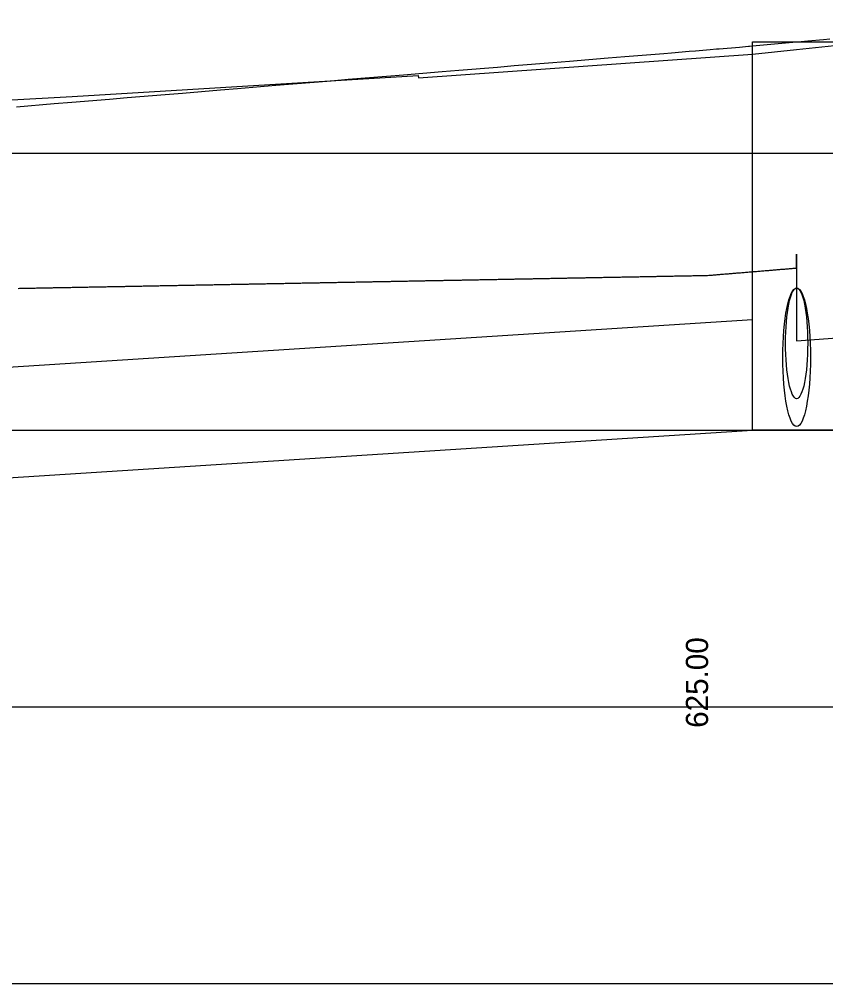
# Model space of a CAD drawing. Extents: x 2254979 to 2278074, y 13790855 to 13792793.
# Drawn here: x 2260664.4 to 2260737.2, y 13792141.4 to 13792228.5 of the extents above; entities that cross this region are included whole.
import ezdxf

# ---------------------------------------------------------------- set-up
doc = ezdxf.new("R2010")
doc.units = 0
for name, color, linetype in [('blank4', 7, 'Continuous'), ('D_DRN_PROF_HGL', 7, 'Continuous'), ('D_PROF_1', 7, 'Continuous'), ('D_PROF_NOTES_1', 7, 'Continuous'), ('Drain_PipeInside', 7, 'Continuous'), ('E_Terrain', 7, 'Continuous'), ('Inlet', 7, 'Continuous'), ('z - Construction', 7, 'Continuous')]:
    doc.layers.add(name, color=color, linetype=linetype)

msp = doc.modelspace()

# ---------------------------------------------------------------- linework, layer by layer
at = {"layer": 'blank4'}
msp.add_lwpolyline([(2259960.685, 13792141.443), (2259960.685, 13792316.443), (2261351.477, 13792316.443), (2261351.477, 13792141.443)], close=True, dxfattribs=at)
at = {"layer": 'D_DRN_PROF_HGL'}
msp.add_line((2260734.572, 13792207.324), (2260734.572, 13792199.492), dxfattribs=at)
for points in [[(2260664.271, 13792204.243), (2260664.382, 13792204.246), (2260664.493, 13792204.248), (2260664.603, 13792204.25), (2260664.714, 13792204.252), (2260664.824, 13792204.254), (2260664.935, 13792204.256), (2260665.045, 13792204.258), (2260665.156, 13792204.26), (2260665.267, 13792204.262), (2260665.377, 13792204.264), (2260665.488, 13792204.266), (2260665.598, 13792204.268), (2260665.709, 13792204.27), (2260665.819, 13792204.273), (2260665.93, 13792204.275), (2260666.041, 13792204.277), (2260666.151, 13792204.279), (2260666.262, 13792204.281), (2260666.372, 13792204.283), (2260666.483, 13792204.285), (2260666.593, 13792204.287), (2260666.704, 13792204.289), (2260666.815, 13792204.291), (2260666.925, 13792204.293), (2260667.036, 13792204.295), (2260667.146, 13792204.298), (2260667.257, 13792204.3), (2260667.367, 13792204.302), (2260667.478, 13792204.304), (2260667.589, 13792204.306), (2260667.699, 13792204.308), (2260667.81, 13792204.31), (2260667.92, 13792204.312), (2260668.031, 13792204.314), (2260668.141, 13792204.316), (2260668.252, 13792204.318), (2260668.363, 13792204.32), (2260668.473, 13792204.322), (2260668.584, 13792204.325), (2260668.694, 13792204.327), (2260668.805, 13792204.329), (2260668.916, 13792204.331), (2260669.026, 13792204.333), (2260669.137, 13792204.335), (2260669.247, 13792204.337), (2260669.358, 13792204.339), (2260669.468, 13792204.341), (2260669.579, 13792204.343), (2260669.69, 13792204.345), (2260669.8, 13792204.347), (2260669.911, 13792204.349), (2260670.021, 13792204.352), (2260670.132, 13792204.354), (2260670.242, 13792204.356), (2260670.353, 13792204.358), (2260670.464, 13792204.36), (2260670.574, 13792204.362), (2260670.685, 13792204.364), (2260670.795, 13792204.366), (2260670.906, 13792204.368), (2260671.016, 13792204.37), (2260671.127, 13792204.372), (2260671.238, 13792204.374), (2260671.348, 13792204.376), (2260671.459, 13792204.379), (2260671.569, 13792204.381), (2260671.68, 13792204.383), (2260671.79, 13792204.385), (2260671.901, 13792204.387), (2260672.012, 13792204.389), (2260672.122, 13792204.391), (2260672.233, 13792204.393), (2260672.343, 13792204.395), (2260672.454, 13792204.397), (2260672.564, 13792204.399), (2260672.675, 13792204.401), (2260672.786, 13792204.404), (2260672.896, 13792204.406), (2260673.007, 13792204.408), (2260673.117, 13792204.41), (2260673.228, 13792204.412), (2260673.338, 13792204.414), (2260673.449, 13792204.416), (2260673.56, 13792204.418), (2260673.67, 13792204.42), (2260673.781, 13792204.422), (2260673.891, 13792204.424), (2260674.002, 13792204.426), (2260674.113, 13792204.428), (2260674.223, 13792204.431), (2260674.334, 13792204.433), (2260674.444, 13792204.435), (2260674.555, 13792204.437), (2260674.665, 13792204.439), (2260674.776, 13792204.441), (2260674.887, 13792204.443), (2260674.997, 13792204.445), (2260675.108, 13792204.447), (2260675.218, 13792204.449), (2260675.329, 13792204.451), (2260675.439, 13792204.453), (2260675.55, 13792204.455), (2260675.661, 13792204.458), (2260675.771, 13792204.46), (2260675.882, 13792204.462), (2260675.992, 13792204.464), (2260676.103, 13792204.466), (2260676.213, 13792204.468), (2260676.324, 13792204.47), (2260676.435, 13792204.472), (2260676.545, 13792204.474), (2260676.656, 13792204.476), (2260676.766, 13792204.478), (2260676.877, 13792204.48), (2260676.987, 13792204.483), (2260677.098, 13792204.485), (2260677.209, 13792204.487), (2260677.319, 13792204.489), (2260677.43, 13792204.491), (2260677.54, 13792204.493), (2260677.651, 13792204.495), (2260677.761, 13792204.497), (2260677.872, 13792204.499), (2260677.983, 13792204.501), (2260678.093, 13792204.503), (2260678.204, 13792204.505), (2260678.314, 13792204.507), (2260678.425, 13792204.51), (2260678.535, 13792204.512), (2260678.646, 13792204.514), (2260678.757, 13792204.516), (2260678.867, 13792204.518), (2260678.978, 13792204.52), (2260679.088, 13792204.522), (2260679.199, 13792204.524), (2260679.31, 13792204.526), (2260679.42, 13792204.528), (2260679.531, 13792204.53), (2260679.641, 13792204.532), (2260679.752, 13792204.534), (2260679.862, 13792204.537), (2260679.973, 13792204.539), (2260680.084, 13792204.541), (2260680.194, 13792204.543), (2260680.305, 13792204.545), (2260680.415, 13792204.547), (2260680.526, 13792204.549), (2260680.636, 13792204.551), (2260680.747, 13792204.553), (2260680.858, 13792204.555), (2260680.968, 13792204.557), (2260681.079, 13792204.559), (2260681.189, 13792204.561), (2260681.3, 13792204.564), (2260681.41, 13792204.566), (2260681.521, 13792204.568), (2260681.632, 13792204.57), (2260681.742, 13792204.572), (2260681.853, 13792204.574), (2260681.963, 13792204.576), (2260682.074, 13792204.578), (2260682.184, 13792204.58), (2260682.295, 13792204.582), (2260682.406, 13792204.584), (2260682.516, 13792204.586), (2260682.627, 13792204.589), (2260682.737, 13792204.591), (2260682.848, 13792204.593), (2260682.958, 13792204.595), (2260683.069, 13792204.597), (2260683.18, 13792204.599), (2260683.29, 13792204.601), (2260683.401, 13792204.603), (2260683.511, 13792204.605), (2260683.622, 13792204.607), (2260683.732, 13792204.609), (2260683.843, 13792204.611), (2260683.954, 13792204.613), (2260684.064, 13792204.616), (2260684.175, 13792204.618), (2260684.285, 13792204.62), (2260684.396, 13792204.622), (2260684.507, 13792204.624), (2260684.617, 13792204.626), (2260684.728, 13792204.628), (2260684.838, 13792204.63), (2260684.949, 13792204.632), (2260685.059, 13792204.634), (2260685.17, 13792204.636), (2260685.281, 13792204.638), (2260685.391, 13792204.64), (2260685.502, 13792204.643), (2260685.612, 13792204.645), (2260685.723, 13792204.647), (2260685.833, 13792204.649), (2260685.944, 13792204.651), (2260686.055, 13792204.653), (2260686.165, 13792204.655), (2260686.276, 13792204.657), (2260686.386, 13792204.659), (2260686.497, 13792204.661), (2260686.607, 13792204.663), (2260686.718, 13792204.665), (2260686.829, 13792204.667), (2260686.939, 13792204.67), (2260687.05, 13792204.672), (2260687.16, 13792204.674), (2260687.271, 13792204.676), (2260687.381, 13792204.678), (2260687.492, 13792204.68), (2260687.603, 13792204.682), (2260687.713, 13792204.684), (2260687.824, 13792204.686), (2260687.934, 13792204.688), (2260688.045, 13792204.69), (2260688.155, 13792204.692), (2260688.266, 13792204.695), (2260688.377, 13792204.697), (2260688.487, 13792204.699), (2260688.598, 13792204.701), (2260688.708, 13792204.703), (2260688.819, 13792204.705), (2260688.929, 13792204.707), (2260689.04, 13792204.709), (2260689.151, 13792204.711), (2260689.261, 13792204.713), (2260689.372, 13792204.715), (2260689.482, 13792204.717), (2260689.593, 13792204.719), (2260689.704, 13792204.722), (2260689.814, 13792204.724), (2260689.925, 13792204.726), (2260690.035, 13792204.728), (2260690.146, 13792204.73), (2260690.256, 13792204.732), (2260690.367, 13792204.734), (2260690.478, 13792204.736), (2260690.588, 13792204.738), (2260690.699, 13792204.74), (2260690.809, 13792204.742), (2260690.92, 13792204.744), (2260691.03, 13792204.746), (2260691.141, 13792204.749), (2260691.252, 13792204.751), (2260691.362, 13792204.753), (2260691.473, 13792204.755), (2260691.583, 13792204.757), (2260691.694, 13792204.759), (2260691.804, 13792204.761), (2260691.915, 13792204.763), (2260692.026, 13792204.765), (2260692.136, 13792204.767), (2260692.247, 13792204.769), (2260692.357, 13792204.771), (2260692.468, 13792204.774), (2260692.578, 13792204.776), (2260692.689, 13792204.778), (2260692.8, 13792204.78), (2260692.91, 13792204.782), (2260693.021, 13792204.784), (2260693.131, 13792204.786), (2260693.242, 13792204.788), (2260693.352, 13792204.79), (2260693.463, 13792204.792), (2260693.574, 13792204.794), (2260693.684, 13792204.796), (2260693.795, 13792204.798), (2260693.905, 13792204.801), (2260694.016, 13792204.803), (2260694.126, 13792204.805), (2260694.237, 13792204.807), (2260694.348, 13792204.809), (2260694.458, 13792204.811), (2260694.569, 13792204.813), (2260694.679, 13792204.815), (2260694.79, 13792204.817), (2260694.901, 13792204.819), (2260695.011, 13792204.821), (2260695.122, 13792204.823), (2260695.232, 13792204.825), (2260695.343, 13792204.828), (2260695.453, 13792204.83), (2260695.564, 13792204.832), (2260695.675, 13792204.834), (2260695.785, 13792204.836), (2260695.896, 13792204.838), (2260696.006, 13792204.84), (2260696.117, 13792204.842), (2260696.227, 13792204.844), (2260696.338, 13792204.846), (2260696.449, 13792204.848), (2260696.559, 13792204.85), (2260696.67, 13792204.852), (2260696.78, 13792204.855), (2260696.891, 13792204.857), (2260697.001, 13792204.859), (2260697.112, 13792204.861), (2260697.223, 13792204.863), (2260697.333, 13792204.865), (2260697.444, 13792204.867), (2260697.554, 13792204.869), (2260697.665, 13792204.871), (2260697.775, 13792204.873), (2260697.886, 13792204.875), (2260697.997, 13792204.877), (2260698.107, 13792204.88), (2260698.218, 13792204.882), (2260698.328, 13792204.884), (2260698.439, 13792204.886), (2260698.549, 13792204.888), (2260698.66, 13792204.89), (2260698.771, 13792204.892), (2260698.881, 13792204.894), (2260698.992, 13792204.896), (2260699.102, 13792204.898), (2260699.213, 13792204.9), (2260699.323, 13792204.902), (2260699.434, 13792204.904), (2260699.545, 13792204.907), (2260699.655, 13792204.909), (2260699.766, 13792204.911), (2260699.876, 13792204.913), (2260699.987, 13792204.915), (2260700.098, 13792204.917), (2260700.208, 13792204.919), (2260700.319, 13792204.921), (2260700.429, 13792204.923), (2260700.54, 13792204.925), (2260700.65, 13792204.927), (2260700.761, 13792204.929), (2260700.872, 13792204.931), (2260700.982, 13792204.934), (2260701.093, 13792204.936), (2260701.203, 13792204.938), (2260701.314, 13792204.94), (2260701.424, 13792204.942), (2260701.535, 13792204.944), (2260701.646, 13792204.946), (2260701.756, 13792204.948), (2260701.867, 13792204.95), (2260701.977, 13792204.952), (2260702.088, 13792204.954), (2260702.198, 13792204.956), (2260702.309, 13792204.959), (2260702.42, 13792204.961), (2260702.53, 13792204.963), (2260702.641, 13792204.965), (2260702.751, 13792204.967), (2260702.862, 13792204.969), (2260702.972, 13792204.971), (2260703.083, 13792204.973), (2260703.194, 13792204.975), (2260703.304, 13792204.977), (2260703.415, 13792204.979), (2260703.525, 13792204.981), (2260703.636, 13792204.983), (2260703.746, 13792204.986), (2260703.857, 13792204.988), (2260703.968, 13792204.99), (2260704.078, 13792204.992), (2260704.189, 13792204.994), (2260704.299, 13792204.996), (2260704.41, 13792204.998), (2260704.52, 13792205), (2260704.631, 13792205.002), (2260704.742, 13792205.004), (2260704.852, 13792205.006), (2260704.963, 13792205.008), (2260705.073, 13792205.01), (2260705.184, 13792205.013), (2260705.294, 13792205.015), (2260705.405, 13792205.017), (2260705.516, 13792205.019), (2260705.626, 13792205.021), (2260705.737, 13792205.023), (2260705.847, 13792205.025), (2260705.958, 13792205.027), (2260706.069, 13792205.029), (2260706.179, 13792205.031), (2260706.29, 13792205.033), (2260706.4, 13792205.035), (2260706.511, 13792205.037), (2260706.621, 13792205.04), (2260706.732, 13792205.042), (2260706.843, 13792205.044), (2260706.953, 13792205.046), (2260707.064, 13792205.048), (2260707.174, 13792205.05), (2260707.285, 13792205.052), (2260707.395, 13792205.054), (2260707.506, 13792205.056), (2260707.617, 13792205.058), (2260707.727, 13792205.06), (2260707.838, 13792205.062), (2260707.948, 13792205.065), (2260708.059, 13792205.067), (2260708.169, 13792205.069), (2260708.28, 13792205.071), (2260708.391, 13792205.073), (2260708.501, 13792205.075), (2260708.612, 13792205.077), (2260708.722, 13792205.079), (2260708.833, 13792205.081), (2260708.943, 13792205.083), (2260709.054, 13792205.085), (2260709.165, 13792205.087), (2260709.275, 13792205.089), (2260709.386, 13792205.092), (2260709.496, 13792205.094), (2260709.607, 13792205.096), (2260709.717, 13792205.098), (2260709.828, 13792205.1), (2260709.939, 13792205.102), (2260710.049, 13792205.104), (2260710.16, 13792205.106), (2260710.27, 13792205.108), (2260710.381, 13792205.11), (2260710.491, 13792205.112), (2260710.602, 13792205.114), (2260710.713, 13792205.116), (2260710.823, 13792205.119), (2260710.934, 13792205.121), (2260711.044, 13792205.123), (2260711.155, 13792205.125), (2260711.266, 13792205.127), (2260711.376, 13792205.129), (2260711.487, 13792205.131), (2260711.597, 13792205.133), (2260711.708, 13792205.135), (2260711.818, 13792205.137), (2260711.929, 13792205.139), (2260712.04, 13792205.141), (2260712.15, 13792205.144), (2260712.261, 13792205.146), (2260712.371, 13792205.148), (2260712.482, 13792205.15), (2260712.592, 13792205.152), (2260712.703, 13792205.154), (2260712.814, 13792205.156), (2260712.924, 13792205.158), (2260713.035, 13792205.16), (2260713.145, 13792205.162), (2260713.256, 13792205.164), (2260713.366, 13792205.166), (2260713.477, 13792205.168), (2260713.588, 13792205.171), (2260713.698, 13792205.173), (2260713.809, 13792205.175), (2260713.919, 13792205.177), (2260714.03, 13792205.179), (2260714.14, 13792205.181), (2260714.251, 13792205.183), (2260714.362, 13792205.185), (2260714.472, 13792205.187), (2260714.583, 13792205.189), (2260714.693, 13792205.191), (2260714.804, 13792205.193), (2260714.914, 13792205.195), (2260715.025, 13792205.198), (2260715.136, 13792205.2), (2260715.246, 13792205.202), (2260715.357, 13792205.204), (2260715.467, 13792205.206), (2260715.578, 13792205.208), (2260715.688, 13792205.21), (2260715.799, 13792205.212), (2260715.91, 13792205.214), (2260716.02, 13792205.216), (2260716.131, 13792205.218), (2260716.241, 13792205.22), (2260716.352, 13792205.222), (2260716.463, 13792205.225), (2260716.573, 13792205.227), (2260716.684, 13792205.229), (2260716.794, 13792205.231), (2260716.905, 13792205.233), (2260717.015, 13792205.235), (2260717.126, 13792205.237), (2260717.237, 13792205.239), (2260717.347, 13792205.241), (2260717.458, 13792205.243), (2260717.568, 13792205.245), (2260717.679, 13792205.247), (2260717.789, 13792205.25), (2260717.9, 13792205.252), (2260718.011, 13792205.254), (2260718.121, 13792205.256), (2260718.232, 13792205.258), (2260718.342, 13792205.26), (2260718.453, 13792205.262), (2260718.563, 13792205.264), (2260718.674, 13792205.266), (2260718.785, 13792205.268), (2260718.895, 13792205.27), (2260719.006, 13792205.272), (2260719.116, 13792205.274), (2260719.227, 13792205.277), (2260719.337, 13792205.279), (2260719.448, 13792205.281), (2260719.559, 13792205.283), (2260719.669, 13792205.285), (2260719.78, 13792205.287), (2260719.89, 13792205.289), (2260720.001, 13792205.291), (2260720.111, 13792205.293), (2260720.222, 13792205.295), (2260720.333, 13792205.297), (2260720.443, 13792205.299), (2260720.554, 13792205.301), (2260720.664, 13792205.304), (2260720.775, 13792205.306), (2260720.885, 13792205.308), (2260720.996, 13792205.31), (2260721.107, 13792205.312), (2260721.217, 13792205.314), (2260721.328, 13792205.316), (2260721.438, 13792205.318), (2260721.549, 13792205.32), (2260721.66, 13792205.322), (2260721.77, 13792205.324), (2260721.881, 13792205.326), (2260721.991, 13792205.328), (2260722.102, 13792205.331), (2260722.212, 13792205.333), (2260722.323, 13792205.335), (2260722.434, 13792205.337), (2260722.544, 13792205.339), (2260722.655, 13792205.341), (2260722.765, 13792205.343), (2260722.876, 13792205.345), (2260722.986, 13792205.347), (2260723.097, 13792205.349), (2260723.208, 13792205.351), (2260723.318, 13792205.353), (2260723.429, 13792205.356), (2260723.539, 13792205.358), (2260723.65, 13792205.36), (2260723.76, 13792205.362), (2260723.871, 13792205.364), (2260723.982, 13792205.366), (2260724.092, 13792205.368), (2260724.203, 13792205.37), (2260724.313, 13792205.372), (2260724.424, 13792205.374), (2260724.534, 13792205.376), (2260724.645, 13792205.378), (2260724.756, 13792205.38), (2260724.866, 13792205.383), (2260724.977, 13792205.385), (2260725.087, 13792205.387), (2260725.198, 13792205.389), (2260725.308, 13792205.391), (2260725.419, 13792205.393), (2260725.53, 13792205.395), (2260725.64, 13792205.397), (2260725.751, 13792205.399), (2260725.861, 13792205.401), (2260725.972, 13792205.403), (2260726.082, 13792205.405), (2260726.193, 13792205.407), (2260726.304, 13792205.41), (2260726.414, 13792205.412), (2260726.525, 13792205.414), (2260726.635, 13792205.42), (2260726.746, 13792205.429), (2260726.857, 13792205.438), (2260726.967, 13792205.447), (2260727.078, 13792205.456), (2260727.188, 13792205.466), (2260727.299, 13792205.475), (2260727.409, 13792205.484), (2260727.52, 13792205.493), (2260727.631, 13792205.502), (2260727.741, 13792205.511), (2260727.852, 13792205.521), (2260727.962, 13792205.53), (2260728.073, 13792205.539), (2260728.183, 13792205.548), (2260728.294, 13792205.557), (2260728.405, 13792205.566), (2260728.515, 13792205.576), (2260728.626, 13792205.585), (2260728.736, 13792205.594), (2260728.847, 13792205.603), (2260728.957, 13792205.612), (2260729.068, 13792205.621), (2260729.179, 13792205.63), (2260729.289, 13792205.64), (2260729.4, 13792205.649), (2260729.51, 13792205.658), (2260729.621, 13792205.667), (2260729.731, 13792205.676), (2260729.842, 13792205.685), (2260729.953, 13792205.695), (2260730.063, 13792205.704), (2260730.174, 13792205.713), (2260730.284, 13792205.722), (2260730.395, 13792205.731), (2260730.505, 13792205.74), (2260730.616, 13792205.75), (2260730.727, 13792205.759), (2260730.837, 13792205.768), (2260730.948, 13792205.777), (2260731.058, 13792205.786), (2260731.169, 13792205.795), (2260731.279, 13792205.804), (2260731.39, 13792205.814), (2260731.501, 13792205.823), (2260731.611, 13792205.832), (2260731.722, 13792205.841), (2260731.832, 13792205.85), (2260731.943, 13792205.859), (2260732.054, 13792205.869), (2260732.164, 13792205.878), (2260732.275, 13792205.887), (2260732.385, 13792205.896), (2260732.496, 13792205.905), (2260732.606, 13792205.914), (2260732.717, 13792205.924), (2260732.828, 13792205.933), (2260732.938, 13792205.942), (2260733.049, 13792205.951), (2260733.159, 13792205.96), (2260733.27, 13792205.969), (2260733.38, 13792205.978), (2260733.491, 13792205.988), (2260733.602, 13792205.997), (2260733.712, 13792206.006), (2260733.823, 13792206.015), (2260733.933, 13792206.024), (2260734.044, 13792206.033), (2260734.154, 13792206.043), (2260734.265, 13792206.052), (2260734.376, 13792206.061), (2260734.486, 13792206.07), (2260734.572, 13792206.076), (2260734.572, 13792207.324)], [(2260734.572, 13792199.492), (2260765.973, 13792201.833)]]:
    msp.add_lwpolyline(points, dxfattribs=at)
at = {"layer": 'D_PROF_1'}
msp.add_lwpolyline([(2260664.12, 13792220.649), (2260667.527, 13792220.928), (2260669.112, 13792221.06), (2260672.531, 13792221.34), (2260674.105, 13792221.472), (2260677.535, 13792221.753), (2260679.099, 13792221.883), (2260682.538, 13792222.165), (2260684.093, 13792222.295), (2260687.542, 13792222.578), (2260689.089, 13792222.707), (2260692.545, 13792222.99), (2260694.084, 13792223.119), (2260697.549, 13792223.402), (2260699.08, 13792223.53), (2260702.552, 13792223.815), (2260704.077, 13792223.942), (2260707.556, 13792224.227), (2260709.074, 13792224.354), (2260712.559, 13792224.64), (2260714.071, 13792224.766), (2260717.563, 13792225.052), (2260719.069, 13792225.177), (2260722.566, 13792225.464), (2260723.263, 13792225.522), (2260724.865, 13792225.654), (2260725.443, 13792225.702), (2260726.77, 13792225.812), (2260727.326, 13792225.859), (2260727.57, 13792225.879), (2260729.418, 13792226.038), (2260730.218, 13792226.105), (2260730.288, 13792226.111), (2260730.318, 13792226.114), (2260730.572, 13792226.136), (2260730.572, 13792226.136), (2260731.901, 13792226.255), (2260732.572, 13792226.312), (2260734.572, 13792226.495), (2260734.572, 13792226.495), (2260734.69, 13792226.506), (2260735.569, 13792226.584), (2260735.579, 13792226.585), (2260735.584, 13792226.585), (2260736.998, 13792226.719), (2260737.572, 13792226.771)], dxfattribs=at)
at = {"layer": 'Drain_PipeInside'}
for p, q in [((2260581.47, 13792191.898), (2260730.572, 13792201.443)), ((2260581.47, 13792181.898), (2260730.572, 13792191.443))]:
    msp.add_line(p, q, dxfattribs=at)
for centre, major_axis in [((2260734.572, 13792198.016), (0, 6.25)), ((2260734.572, 13792199.278), (0, 5))]:
    msp.add_ellipse(centre, major_axis=major_axis, ratio=0.2, dxfattribs=at)
at = {"layer": 'E_Terrain'}
msp.add_lwpolyline([(2260577.47, 13792216.305), (2260581.47, 13792216.628), (2260581.47, 13792216.628), (2260590.632, 13792217.322), (2260600.206, 13792217.86), (2260603.32, 13792218.014), (2260638.64, 13792219.874), (2260669.149, 13792221.582), (2260700.382, 13792223.474), (2260700.415, 13792223.257), (2260730.572, 13792225.385), (2260730.572, 13792225.385), (2260734.572, 13792225.81), (2260734.572, 13792225.81), (2260738.572, 13792226.234)], dxfattribs=at)
at = {"layer": 'Inlet'}
msp.add_lwpolyline([(2260730.572, 13792226.495), (2260738.572, 13792226.495), (2260738.572, 13792191.443), (2260730.572, 13792191.443)], close=True, dxfattribs=at)
at = {"layer": 'z - Construction'}
for p, q in [((2259960.685, 13792216.443), (2261351.477, 13792216.443)), ((2259960.685, 13792191.443), (2261351.477, 13792191.443)), ((2259960.685, 13792166.443), (2261351.477, 13792166.443))]:
    msp.add_line(p, q, dxfattribs=at)

# ---------------------------------------------------------------- texts
at = {"layer": 'D_PROF_NOTES_1'}
msp.add_text('625.00', height=2, rotation=90, dxfattribs=at).set_placement((2260726.572, 13792164.552))

doc.saveas('drawing.dxf')
